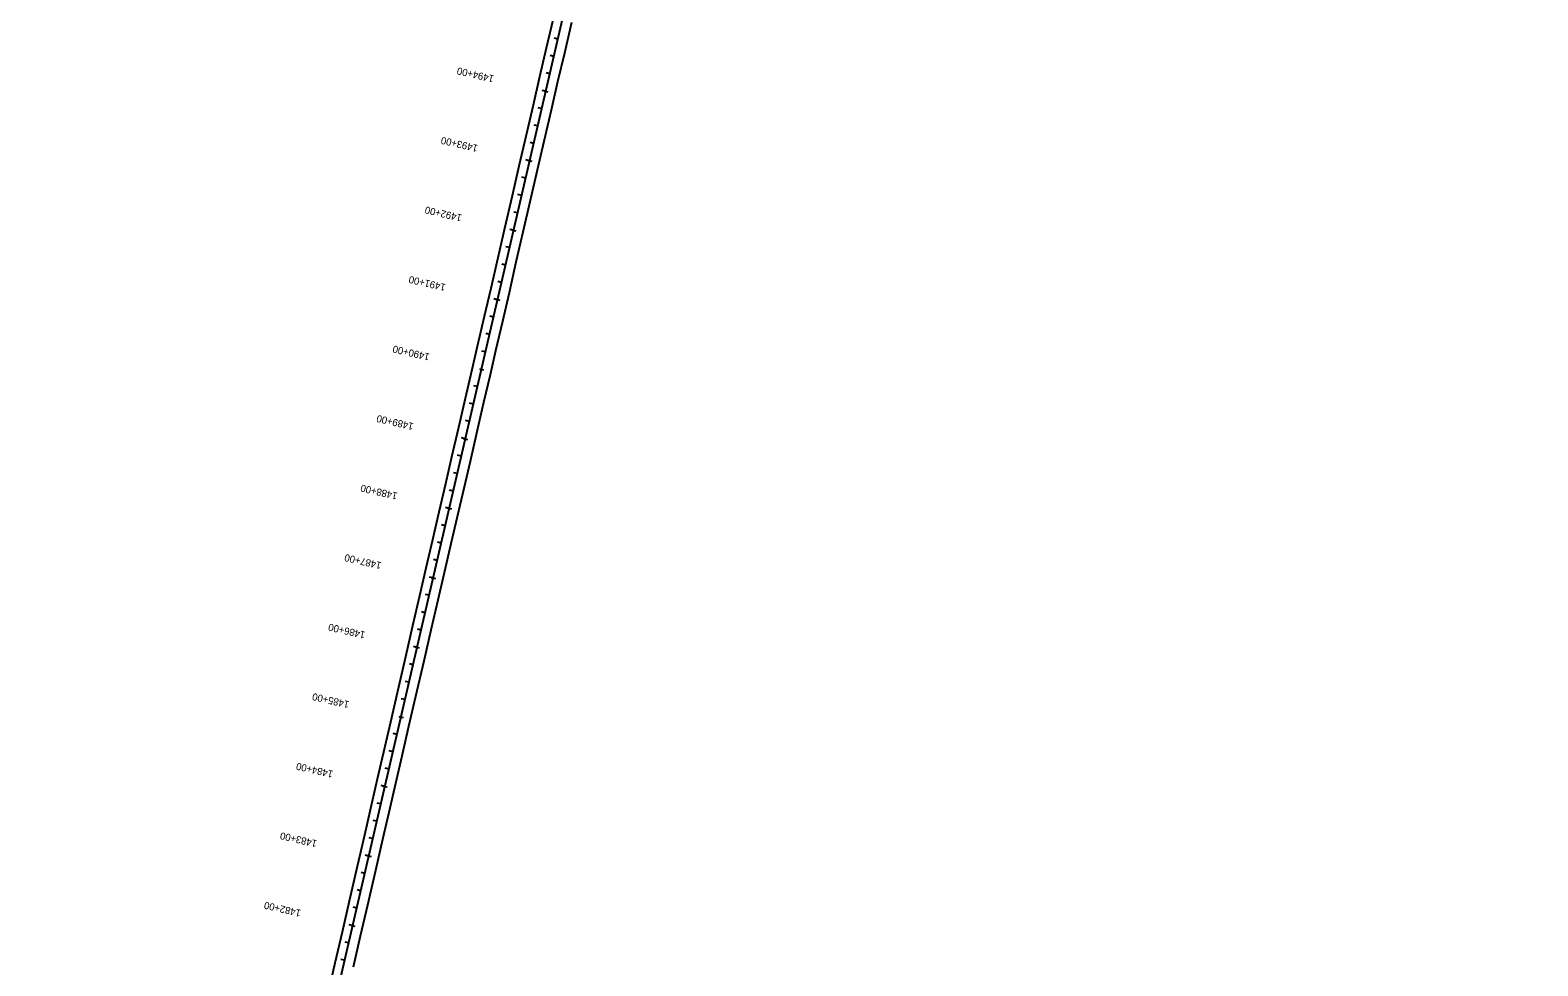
# Model space of a CAD drawing. Extents: x 21596470 to 21601942, y 8263806 to 8275912.
# Drawn here: x 21596601 to 21598714, y 8268550 to 8269862 of the extents above; entities that cross this region are included whole.
import ezdxf

# ---------------------------------------------------------------- set-up
doc = ezdxf.new("R2010")
doc.units = 0
for name, color, linetype in [('Level 1', 7, 'Continuous'), ('Level 20', 7, 'Continuous'), ('SurTxtLeaderLine', 7, 'Continuous'), ('SurTxtSurveyInformation', 7, 'Continuous'), ('wetNoteSoil', 7, 'Continuous')]:
    doc.layers.add(name, color=color, linetype=linetype)

msp = doc.modelspace()

# ---------------------------------------------------------------- linework, layer by layer
at = {"layer": 'Level 1'}
for p, q in [((21597324.1, 8269776), (21597318.8, 8269777.2)), ((21597301.5, 8269678.6), (21597296.2, 8269679.8)), ((21597279, 8269581.2), (21597273.7, 8269582.4)), ((21597256.5, 8269483.7), (21597251.1, 8269485)), ((21597230.9, 8269387), (21597236.9, 8269385.6)), ((21597211.4, 8269288.9), (21597206.1, 8269290.1)), ((21597188.8, 8269191.5), (21597183.5, 8269192.7)), ((21597166.3, 8269094), (21597161, 8269095.3)), ((21597143.8, 8268996.6), (21597138.4, 8268997.8)), ((21597118.2, 8268899.9), (21597124.2, 8268898.5)), ((21597098.7, 8268801.7), (21597093.4, 8268803)), ((21597076.1, 8268704.3), (21597070.8, 8268705.6)), ((21597053.6, 8268606.9), (21597048.3, 8268608.1))]:
    msp.add_line(p, q, dxfattribs=at)
at = {"layer": 'Level 20'}
for p, q in [((21596601.4, 8266652.3), (21598714.2, 8275785)), ((21596728.7, 8267202.6), (21598588.8, 8275242.6))]:
    msp.add_line(p, q, dxfattribs=at)
at = {"layer": 'SurTxtLeaderLine'}
msp.add_lwpolyline([(21597054.4, 8268549), (21597064.4, 8268592.7), (21597074.5, 8268636), (21597085.7, 8268684.3), (21597095.8, 8268728.1), (21597104.4, 8268765.8), (21597113.8, 8268806.3), (21597122.8, 8268844.9), (21597132.2, 8268886.4), (21597142, 8268928.3), (21597153.5, 8268977.9), (21597163.5, 8269021.4), (21597173.2, 8269063.1), (21597182, 8269101.4), (21597191.3, 8269142.2), (21597200.2, 8269180.2), (21597209.4, 8269220), (21597218.3, 8269257.7), (21597227.8, 8269299.2), (21597237.2, 8269340.2), (21597246.3, 8269379), (21597254, 8269412.5), (21597263.6, 8269453.9), (21597273, 8269494.1), (21597282.7, 8269536.7), (21597292.5, 8269578.9), (21597302.6, 8269623.3), (21597312.5, 8269665.7), (21597321.7, 8269706.2), (21597332, 8269749.9), (21597341, 8269789.7), (21597350.5, 8269829.6), (21597360.5, 8269872.9)], dxfattribs=at)
at = {"layer": 'SurTxtSurveyInformation'}
msp.add_lwpolyline([(21597018.4, 8268509.5), (21597028.9, 8268554.8), (21597038.9, 8268598), (21597049, 8268641.7), (21597060.2, 8268690), (21597070.3, 8268733.8), (21597078.9, 8268771.4), (21597088.4, 8268812.3), (21597097.1, 8268850.5), (21597107, 8268892.5), (21597116.6, 8268935.2), (21597127.7, 8268983.7), (21597137.8, 8269027.3), (21597147.5, 8269069.3), (21597156.4, 8269108.1), (21597165.8, 8269147.9), (21597174.8, 8269186.8), (21597183.8, 8269226.2), (21597192.4, 8269263.6), (21597202.1, 8269305.4), (21597211.5, 8269345.8), (21597220.9, 8269386.1), (21597228.4, 8269418.8), (21597238.2, 8269461), (21597247.3, 8269500.2), (21597257.2, 8269543.1), (21597266.6, 8269584.3), (21597277.5, 8269629.7), (21597286.9, 8269671.5), (21597296.6, 8269712.9), (21597306.6, 8269756.7), (21597315.7, 8269796.4), (21597324.9, 8269836.6), (21597334.6, 8269877.9)], dxfattribs=at)
at = {"layer": 'wetNoteSoil'}
for p, q in [((21597341, 8269849.1), (21597335.7, 8269850.3)), ((21597335.3, 8269824.7), (21597330, 8269826)), ((21597329.7, 8269800.4), (21597324.4, 8269801.6)), ((21597321.1, 8269776.7), (21597327.1, 8269775.3)), ((21597318.4, 8269751.7), (21597313.1, 8269752.9)), ((21597312.8, 8269727.3), (21597307.5, 8269728.5)), ((21597307.2, 8269702.9), (21597301.9, 8269704.2)), ((21597298.6, 8269679.3), (21597304.5, 8269677.9)), ((21597295.9, 8269654.2), (21597290.6, 8269655.5)), ((21597290.3, 8269629.9), (21597284.9, 8269631.1)), ((21597284.6, 8269605.5), (21597279.3, 8269606.7)), ((21597276, 8269581.9), (21597282, 8269580.5)), ((21597273.4, 8269556.8), (21597268, 8269558)), ((21597267.7, 8269532.4), (21597262.4, 8269533.7)), ((21597262.1, 8269508.1), (21597256.8, 8269509.3)), ((21597253.5, 8269484.4), (21597259.4, 8269483)), ((21597250.8, 8269459.4), (21597245.5, 8269460.6)), ((21597245.2, 8269435), (21597239.9, 8269436.3)), ((21597239.6, 8269410.7), (21597234.2, 8269411.9)), ((21597230.9, 8269387), (21597236.9, 8269385.6)), ((21597228.3, 8269362), (21597223, 8269363.2)), ((21597222.7, 8269337.6), (21597217.3, 8269338.8)), ((21597217, 8269313.2), (21597211.7, 8269314.5)), ((21597208.4, 8269289.6), (21597214.4, 8269288.2)), ((21597205.7, 8269264.5), (21597200.4, 8269265.8)), ((21597200.1, 8269240.2), (21597194.8, 8269241.4)), ((21597194.5, 8269215.8), (21597189.2, 8269217)), ((21597185.9, 8269192.1), (21597191.8, 8269190.8)), ((21597183.2, 8269167.1), (21597177.9, 8269168.3)), ((21597177.6, 8269142.7), (21597172.3, 8269144)), ((21597171.9, 8269118.4), (21597166.6, 8269119.6)), ((21597163.3, 8269094.7), (21597169.3, 8269093.3)), ((21597160.7, 8269069.7), (21597155.3, 8269070.9)), ((21597155, 8269045.3), (21597149.7, 8269046.5)), ((21597149.4, 8269021), (21597144.1, 8269022.2)), ((21597140.8, 8268997.3), (21597146.7, 8268995.9)), ((21597138.1, 8268972.2), (21597132.8, 8268973.5)), ((21597132.5, 8268947.9), (21597127.2, 8268949.1)), ((21597126.9, 8268923.5), (21597121.5, 8268924.8)), ((21597118.2, 8268899.9), (21597124.2, 8268898.5)), ((21597115.6, 8268874.8), (21597110.3, 8268876)), ((21597110, 8268850.5), (21597104.6, 8268851.7)), ((21597104.3, 8268826.1), (21597099, 8268827.3)), ((21597095.7, 8268802.4), (21597101.7, 8268801.1)), ((21597093, 8268777.4), (21597087.7, 8268778.6)), ((21597087.4, 8268753), (21597082.1, 8268754.3)), ((21597081.8, 8268728.7), (21597076.5, 8268729.9)), ((21597073.2, 8268705), (21597079.1, 8268703.6)), ((21597070.5, 8268680), (21597065.2, 8268681.2)), ((21597064.9, 8268655.6), (21597059.6, 8268656.8)), ((21597059.2, 8268631.3), (21597053.9, 8268632.5)), ((21597050.6, 8268607.6), (21597056.6, 8268606.2)), ((21597048, 8268582.5), (21597042.7, 8268583.8)), ((21597042.3, 8268558.2), (21597037, 8268559.4))]:
    msp.add_line(p, q, dxfattribs=at)

# ---------------------------------------------------------------- texts
at = {"layer": 'Level 1'}
for s, p in [('1490+00', (21597162, 8269408.1)), ('1485+00', (21597049.3, 8268921))]:
    msp.add_text(s, height=10.02, rotation=166.974, dxfattribs=at).set_placement(p)
at = {"layer": 'wetNoteSoil'}
for s, p in [('1494+00', (21597252.1, 8269797.8)), ('1493+00', (21597229.6, 8269700.4)), ('1492+00', (21597207.1, 8269602.9)), ('1491+00', (21597184.5, 8269505.5)), ('1490+00', (21597162, 8269408.1)), ('1489+00', (21597139.4, 8269310.7)), ('1488+00', (21597116.9, 8269213.2)), ('1487+00', (21597094.4, 8269115.8)), ('1486+00', (21597071.8, 8269018.4)), ('1485+00', (21597049.3, 8268921)), ('1484+00', (21597026.7, 8268823.5)), ('1483+00', (21597004.2, 8268726.1)), ('1482+00', (21596981.7, 8268628.7))]:
    msp.add_text(s, height=10.02, rotation=166.974, dxfattribs=at).set_placement(p)

doc.saveas('drawing.dxf')
